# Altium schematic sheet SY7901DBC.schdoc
size 127 x 101 mm
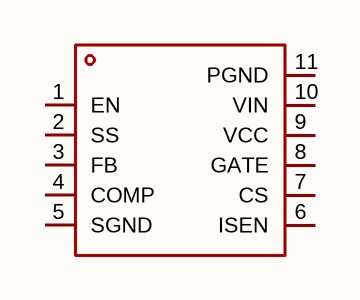
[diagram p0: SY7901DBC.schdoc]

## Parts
U?  sy7901dbc  [DFN-10_L3.0-W3.0-P0.50-BL-EP2.5]  (value not drawn)

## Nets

Not connected (* = marked no-connect by the designer): U? 1(EN) 2(SS) 3(FB) 4(COMP) 5(SGND) 6(ISEN) 7(CS) 8(GATE) 9(VCC) 10(VIN) 11(PGND)

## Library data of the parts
U? = sy7901dbc: 功能类型:升压型;工作电压:3V~25V;输出电压:-;输出电流:-;输出类型:可调;; Manufacturer: Silergy(矽力杰); AddInBom: yes; ModelId: 18def777bd23408db50ca97153a2808f; ModelTransform: 118.11,118.8974,0,0,0,0,0,0,0; Function: 升压型; Voltage - Supply: 3V~25V; Frequency - Switching: 500kHz; Number of Outputs: 1; Topology: SEPIC；升压式；正激式；反激式; Quiescent Current: 170uA; Switch tube (built-in/external): 内置; Output Type: 可调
